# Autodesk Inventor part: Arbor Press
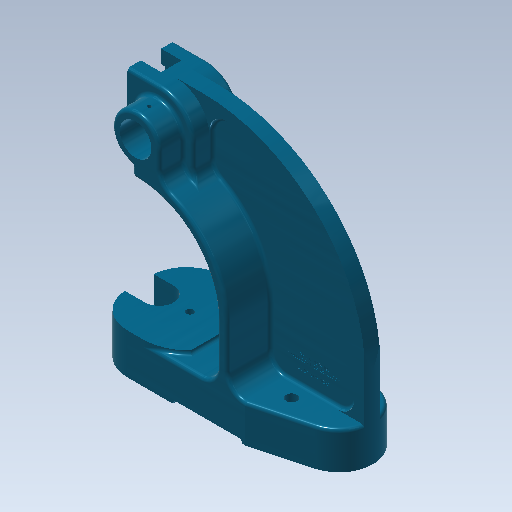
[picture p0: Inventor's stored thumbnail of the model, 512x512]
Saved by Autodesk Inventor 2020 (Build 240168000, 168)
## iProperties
Part Number: Arbor Press
Document SubType Name: Modeling
Created: 2003-11
Designer: Autodesk, Inc.
Manufacturer: Standard
Standards Organization: Custom
Mass: 6013.13 g
Surface Area: 1633.45 cm^2
Volume: 766.003 cm^3
Density: 7.85 g/cm^3
Material: Cast Steel
Appearance: Sky Blue Dark
Control State: 0
Master: False
Checked Out: False
Shininess: 64.0
Length Units: 11272
Angle Units: 11279
Time Units: 11290
Mass Units: 11286
Length Display Precision: 3
Angle Display Precision: 2
Compacted: True
Density: 0.0
Volumn: 0.0
Area: 0.0
PropertySet Name: Model Information
Title: Arbor Press
Author: Autodesk, Inc.
Revision Number: A
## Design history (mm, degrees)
sketch "Sketch7"
  geometry: L1 (0, 0)-(0, 38.1); L2 (0, 38.1)-(79.375, 38.1); L3 (79.375, 38.1)-(79.375, 34.925); L4 (79.375, 34.925)-(117.475, 34.925); L5 (41.275, 165.1)-(11.201, 165.1); L6 (11.201, 165.1)-(11.201, 228.6); L7 (11.201, 228.6)-(66.675, 228.6); L8 (219.075, 76.2)-(219.075, 0); L9 (219.075, 0)-(141.275, 0); L10 (141.275, 0)-(0, 0); L11 (117.475, 34.925)-(117.475, 88.9); A1 r 152.4 centre (66.675, 76.2) between (219.075, 76.2) and (66.675, 228.6); A2 r 76.2 centre (41.275, 88.9) between (117.475, 88.9) and (41.275, 165.1)
  constraints: 22 end point, 8 parallel, 4 point on circle, 4 tangent, 2 centre point, 2 perpendicular, 1 collinear, 1 vertical
  dimensions: "d46" = 79.375 distance of L1.end L2.end; "d47" = 38.1 distance of L1.start L1.end; "d52" = 219.075 distance between parallel lines of L8 L1; "d53" = 228.6 distance between parallel lines of L10 L7; "d54" = 3.175 distance between parallel lines of L4 L2; "d55" = 152.4 radius of A1; "d56" = 76.2 radius of A2; "d57" = 63.5 distance of L5.end L6.end; "d59" = 25.4 horizontal distance of A1.centre A2.centre; "d60" = 30.0736 horizontal distance of A2.centre L5.end
extrude "Extrusion6" new body sketch "Sketch7" distance "d61" = 88.9; taper "d62" = 0 deg
sketch "Sketch8"
  geometry: L1 (207.874, 0)-(55.474, 0) reference; L2 (0, 0)-(55.474, 0) reference; L3 (-11.201, 0)-(68.174, 0) reference; L4 (-11.201, 0)-(-11.201, -88.9) reference; L5 (-11.201, -88.9)-(68.174, -88.9) reference; L6 (207.874, -88.9)-(55.474, -88.9) reference; L7 (207.874, 0)-(207.874, -88.9) reference; L8 (-11.201, -44.45)-(207.874, -44.45); L9 (-11.201, -44.45)-(-11.201, -33.325); L10 (22.123, 0)-(132.907, 0); L11 (132.907, 0)-(184.341, -13.782); L12 (22.123, -88.9)-(132.907, -88.9); L13 (132.907, -88.9)-(184.341, -75.118); L14 (-11.201, -44.45)-(-11.201, -55.575); A1 r 33.325 centre (22.123, -33.325) between (22.123, 0) and (-11.201, -33.325); A2 r 31.75 centre (176.124, -44.45) between (207.874, -44.45) and (184.341, -13.782); A3 r 33.325 centre (22.123, -55.575) between (-11.201, -55.575) and (22.123, -88.9); A4 r 31.75 centre (176.124, -44.45) between (184.341, -75.118) and (207.874, -44.45)
  constraints: 14 end point, 8 point on circle, 5 symmetric about line, 4 centre point, 4 point on line, 4 tangent, 2 midpoint, 1 collinear, 4 other
  dimensions: "d63" = 15 deg angle of L1 L11; "d64" = 33.3248 radius of A1; "d65" = 31.75 radius of A2
extrude "Extrusion7" sketch "Sketch8" extent not by distance; stored distance "d66" = 88.9; taper "d67" = 0 deg
sketch "Sketch9"
  geometry: L1 (141.275, 3.175)-(76.2, 3.175) reference; L2 (144.108, 0)-(195.543, 0) reference; L3 (79.375, 34.925)-(117.475, 34.925) reference; L4 (117.475, 34.925)-(117.475, 88.9) reference; L5 (219.075, 34.925)-(127, 34.925); L6 (219.075, 76.2)-(219.075, 0) reference; L7 (11.201, 228.6)-(11.201, 165.1) reference; L8 (219.075, 34.925)-(219.075, 76.2); L9 (127, 88.9)-(127, 34.925); L10 (73.025, 228.6)-(73.025, 168.529); L11 (33.325, 228.6)-(66.675, 228.6) reference; A1 r 76.2 centre (41.275, 88.9) between (117.475, 88.9) and (41.275, 165.1) reference; A2 r 152.4 centre (66.675, 76.2) between (144.108, 207.463) and (66.675, 228.6) reference; A3 r 152.4 centre (66.675, 76.2) between (195.543, 157.557) and (144.108, 207.463) reference; A4 r 152.401 centre (66.674, 76.2) between (219.075, 76.2) and (195.543, 157.557); A5 r 152.4 centre (66.675, 76.2) between (195.543, 157.557) and (144.108, 207.463); A6 r 85.725 centre (41.275, 88.9) between (127, 88.9) and (73.025, 168.529); A7 r 152.4 centre (66.675, 76.2) between (144.108, 207.463) and (73.025, 228.468)
  constraints: 8 end point, 8 point on circle, 4 centre point, 3 concentric, 2 point on line, 1 collinear
  dimensions: "d86" = 9.525 distance between parallel lines of L9 L4; "d87" = 61.8236 distance between parallel lines of L10 L7; "d88" = 85.725 radius of A6; "d89" = 152.40105 radius of A4
workplane "Work Plane2"
extrude "Extrusion9" cut sketch "Sketch9" distance "d90" = 37.3126; taper "d91" = 0 deg
sketch "Sketch12"
  geometry: L1 (127, 34.925)-(127, 88.9) reference; L2 (144.108, 34.925)-(127, 34.925) reference; L3 (195.543, 34.925)-(144.108, 34.925) reference; L4 (195.543, 34.925)-(218.262, 34.925) reference; L5 (127, 88.9)-(127, 34.925); L6 (218.262, 91.917)-(218.262, 34.925) reference; L7 (208.737, 91.417)-(208.737, 34.925); L8 (66.212, 219.075)-(66.675, 219.075); L9 (208.737, 34.925)-(127, 34.925); L10 (73.025, 168.529)-(73.025, 218.934); L11 (73.025, 228.468)-(73.025, 228.6); A1 r 85.725 centre (41.275, 88.9) between (127, 88.9) and (73.025, 168.529) reference; A2 r 85.725 centre (41.275, 88.9) between (127, 88.9) and (73.025, 168.529); A3 r 152.4 centre (66.675, 76.2) between (195.543, 157.557) and (66.675, 228.6) reference; A4 r 152.401 centre (66.674, 76.2) between (218.262, 91.917) and (195.543, 157.557) reference; A5 r 142.875 centre (66.675, 76.2) between (187.488, 152.472) and (73.025, 218.934); A6 r 142.876 centre (66.674, 76.2) between (208.737, 91.417) and (187.488, 152.472); A7 r 85.725 centre (41.275, 88.9) between (127, 88.9) and (73.025, 168.529) reference; 2 further points; 1 other entity
  constraints: 12 end point, 9 point on circle, 3 centre point, 2 tangent, 1 collinear, 1 concentric, 1 point on line, 1 other
  dimensions: "d93" = 9.525 radial gap between concentric circles of A3 A5; "d94" = 9.525 distance between parallel lines of L6 L7; "d99" = 0 horizontal extent of L10; "d100" = 9.525 radial gap between concentric circles of A4 A6
extrude "Extrusion10" cut sketch "Sketch12" distance "d96" = 3.175; taper "d97" = 0 deg
sketch "Sketch13"
  geometry: L1 (33.325, 165.1)-(11.201, 165.1) reference; L2 (11.201, 228.6)-(11.201, 165.1) reference; L3 (11.201, 228.6)-(33.325, 228.6) reference; L4 (33.325, 228.6)-(66.675, 228.6) reference; L5 (41.275, 165.1)-(33.325, 165.1) reference; L6 (38.1, 165.1)-(38.1, 174.853); L7 (11.201, 196.85)-(77.125, 196.85); L8 (63.5, 196.85)-(63.5, 171.694); L9 (73.025, 168.529)-(73.025, 228.468) reference; L10 (38.1, 165.1)-(11.201, 165.1); L11 (11.201, 165.1)-(11.201, 228.6); L12 (73.025, 228.468)-(73.025, 168.529); L13 (12.066, 228.6)-(66.675, 228.6); A1 r 76.2 centre (41.275, 88.9) between (117.475, 88.9) and (41.275, 165.1) reference; A2 r 152.4 centre (66.675, 76.2) between (73.025, 228.468) and (66.675, 228.6) reference; A3 r 22.225 centre (41.275, 196.85) between (63.5, 196.85) and (38.1, 174.853); A4 r 85.725 centre (41.275, 88.9) between (127, 88.9) and (73.025, 168.529) reference; A5 r 85.725 centre (41.275, 88.9) between (73.025, 168.529) and (63.5, 171.694); A6 r 152.4 centre (66.675, 76.2) between (73.025, 228.468) and (66.675, 228.6)
  constraints: 14 end point, 6 point on circle, 4 perpendicular, 4 point on line, 3 centre point, 3 collinear, 2 concentric, 2 tangent, 1 midpoint
  dimensions: "d101" = 44.45 diameter of A3; "d102" = 30.0736 distance from line of L2 A3.centre; "d103" = 3.175 distance from line of A3.centre L6; "d105" = 9.525 radial gap between concentric circles of A1 A5
extrude "Extrusion11" cut sketch "Sketch13" distance "d106" = 22.225; taper "d107" = 0 deg
mirror "Mirror3"
sketch "Sketch14"
  geometry: L1 (0, 63.5)-(58.272, 63.5) reference; L2 (-8.403, 63.5)-(0, 63.5) reference; L3 (-8.403, 63.5)-(-8.403, 0) reference; L4 (0, 0)-(58.272, 0) reference; L5 (58.272, 0)-(58.272, 63.5) reference; L6 (58.272, 53.975)-(80.497, 53.975) reference; L7 (80.497, 52.504)-(80.497, 10.996) reference; L8 (80.497, 31.75)-(80.497, 53.975) reference; L9 (80.497, 9.753)-(80.497, 0) reference; L10 (80.497, 9.753)-(80.497, 10.996) reference; L11 (80.497, 0)-(58.272, 0) reference; L12 (13.822, 63.5)-(13.822, 9.525); L13 (13.822, 63.5)-(-8.403, 63.5); L14 (-8.403, 63.5)-(-8.403, 9.525); L15 (-8.403, 9.525)-(13.822, 9.525); L16 (0, 0)-(-8.403, 0) reference
  constraints: 8 end point, 3 perpendicular, 1 point on line
  dimensions: "d109" = 44.45 distance between parallel lines of L5 L12; "d111" = 9.525 distance between parallel lines of L4 L15
extrude "Extrusion12" cut sketch "Sketch14" stored distance "d112" = 22.225; taper "d113" = 0 deg
sketch "Sketch16"
  geometry: L1 (-33.325, 174.625)-(-73.025, 174.625) reference; L2 (-33.325, 174.625)-(-33.325, 165.1) reference; L3 (-73.025, 174.625)-(-73.025, 168.529) reference; L4 (-73.025, 168.529)-(-73.025, 174.625); L5 (-73.025, 174.625)-(-41.275, 174.625); A1 r 85.725 centre (-41.275, 88.9) between (-73.025, 168.529) and (-127, 88.9) reference; A2 r 85.725 centre (-41.275, 88.9) between (-41.275, 174.625) and (-73.025, 168.529)
  constraints: 4 end point, 2 collinear, 2 point on circle, 2 tangent, 1 centre point, 1 concentric, 1 point on line
extrude "Extrusion13" cut sketch "Sketch16" distance "d116" = 22.225; taper "d117" = 0 deg
workplane "Work Plane5"
sketch "Sketch17"
  geometry: L1 (11.201, 228.6)-(11.201, 174.625) reference; L2 (66.675, 228.6)-(11.201, 228.6) reference; L3 (73.025, 168.529)-(73.025, 228.468) reference; L4 (11.201, 215.9)-(41.275, 215.9); L5 (41.275, 177.8)-(11.201, 177.8); L6 (33.325, 165.1)-(11.201, 165.1) reference; A1 r 152.4 centre (66.675, 76.2) between (73.025, 228.468) and (66.675, 228.6) reference; A2 r 19.05 centre (41.275, 196.85) between (41.275, 177.8) and (41.275, 215.9)
  constraints: 4 end point, 2 point on circle, 2 point on line, 1 centre point, 1 parallel, 1 tangent
  dimensions: "d120" = 38.1 distance between parallel lines of L5 L4; "d121" = 19.05 radius of A2; "d122" = 12.7 distance of L1.start L4.start; "d123" = 12.7 distance of L6.end L5.end; "d124" = 30.0736 distance from line of L1 A2.centre
extrude "Extrusion14" cut sketch "Sketch17" stored distance "d125" = 25.4; taper "d126" = 0 deg
sketch "Sketch18"
  geometry: C1 r 14.879 at (41.275, 196.85); A1 r 22.225 centre (41.275, 196.85) between (63.5, 196.85) and (33.325, 217.604) reference
  constraints: 1 centre point, 1 coincident
  dimensions: "d127" = 29.758 diameter of C1
extrude "Extrusion15" cut sketch "Sketch18" distance "d128" = 38.1; taper "d129" = 0 deg
sketch "Sketch19"
  geometry: C1 r 9.538 at (41.275, 196.85); A1 r 22.225 centre (41.275, 196.85) between (63.5, 196.85) and (33.325, 217.604) reference; 2 further points
  constraints: 1 centre point, 1 coincident
  dimensions: "d130" = 19.0754 diameter of C1
extrude "Extrusion16" cut sketch "Sketch19" distance "d131" = 25.4; taper "d132" = 0 deg
fillet "Fillet2" dims "d134" = 15.875
fillet "Fillet3" dims "d135" = 15.875
sketch "Sketch20"
  geometry: L1 (11.201, 228.6)-(66.675, 228.6) reference; L2 (73.025, 228.468)-(73.025, 178.646) reference; L3 (41.275, 228.6)-(66.675, 228.6); L4 (73.025, 228.468)-(73.025, 196.85); C1 r 9.538 at (41.275, 196.85) reference; A1 r 31.75 centre (41.275, 196.85) between (73.025, 196.85) and (41.275, 228.6); A2 r 152.4 centre (66.675, 76.2) between (73.025, 228.468) and (66.675, 228.6) reference; A3 r 152.4 centre (66.675, 76.2) between (73.025, 228.468) and (66.675, 228.6)
  constraints: 4 end point, 4 point on circle, 2 centre point, 2 point on line, 2 tangent, 1 coincident, 1 collinear, 1 concentric
extrude "Extrusion17" cut sketch "Sketch20" distance "d136" = 15.0876; taper "d137" = 0 deg
mirror "Mirror4"
fillet "Fillet4" dims "d138" = 15.875
fillet "Fillet5" dims "d139" = 3.175
fillet "Fillet6" dims "d140" = 3.175
fillet "Fillet7" dims "d141" = 15.875
sketch "Sketch22"
  geometry: L1 (-79.375, 55.575)-(-79.375, 33.325) reference; L2 (-46.05, 0)-(0, 0) reference; L3 (-46.05, 88.9)-(0, 88.9) reference; L4 (-79.375, 44.45)-(-18.816, 44.45); L5 (-60.325, 57.944)-(-79.375, 57.944); L6 (-79.375, 30.956)-(-60.325, 30.956); L7 (-79.375, 57.944)-(-79.375, 30.956); A1 r 33.325 centre (-46.05, 55.575) between (-46.05, 88.9) and (-79.375, 55.575) reference; A2 r 33.325 centre (-46.05, 33.325) between (-79.375, 33.325) and (-46.05, 0) reference; A3 r 13.494 centre (-60.325, 44.45) between (-60.325, 30.956) and (-60.325, 57.944)
  constraints: 8 end point, 3 perpendicular, 3 point on line, 2 point on circle, 2 tangent, 1 centre point, 1 midpoint, 1 parallel
  dimensions: "d147" = 26.9875 diameter of A3; "d148" = 19.05 distance of L4.start A3.centre
extrude "Extrusion19" cut sketch "Sketch22" stored distance "d149" = 3.175; taper "d150" = 0 deg
sketch "Sketch23"
  geometry: L1 (0, 88.9)-(0, 0) reference; L2 (-46.05, 0)-(0, 0) reference; L3 (-60.325, 44.45)-(-10.181, 44.45); L4 (0, 13.341)-(0, 0); L5 (0, 0)-(-31.75, 0); A1 r 44.45 centre (-31.75, 44.45) between (-31.75, 0) and (0, 13.341); A2 r 13.494 centre (-60.325, 44.45) between (-60.325, 30.956) and (-60.325, 57.944) reference
  constraints: 6 end point, 3 point on line, 2 point on circle, 1 centre point, 1 parallel, 1 perpendicular
  dimensions: "d151" = 88.9 diameter of A1; "d153" = 28.575 distance of A1.centre L3.start
extrude "Extrusion20" cut sketch "Sketch23" distance "d154" = 3.175; taper "d155" = 0 deg
mirror "Mirror5"
fillet "Fillet10" dims "d157" = 15.875
fillet "Fillet11" dims "d158" = 15.875
fillet "Fillet12" dims "d159" = 15.875
fillet "Fillet15" dims "d162" = 15.875
sketch "Sketch24"
  geometry: L1 (-33.241, 57.944)-(-14.275, 57.944) reference; L2 (-14.275, 30.956)-(-33.241, 30.956) reference; L3 (110.783, 0)-(0, 0) reference; L4 (162.218, 13.782)-(110.783, 0) reference; L5 (110.783, 88.9)-(162.218, 75.118) reference; L6 (110.783, 88.9)-(0, 88.9) reference; L7 (0, 80.975)-(109.74, 80.975); L8 (109.74, 80.975)-(160.167, 67.463); L9 (160.167, 21.437)-(109.74, 7.925); L10 (109.74, 7.925)-(0, 7.925); L11 (-23.221, 23.031)-(-14.275, 23.031); L12 (-14.275, 65.869)-(-23.221, 65.869); A1 r 13.494 centre (-14.275, 44.45) between (-14.275, 30.956) and (-14.275, 57.944) reference; A2 r 33.325 centre (0, 33.325) between (-33.241, 30.956) and (0, 0) reference; A3 r 31.75 centre (154, 44.45) between (162.218, 13.782) and (162.218, 75.118) reference; A4 r 33.325 centre (0, 55.575) between (0, 88.9) and (-33.241, 57.944) reference; A5 r 23.825 centre (154, 44.45) between (160.167, 21.437) and (160.167, 67.463); A6 r 25.4 centre (0, 33.325) between (-23.221, 23.031) and (0, 7.925); A7 r 21.419 centre (-14.275, 44.45) between (-14.275, 23.031) and (-14.275, 65.869); A8 r 25.4 centre (0, 55.575) between (0, 80.975) and (-23.221, 65.869)
  constraints: 12 end point, 8 point on circle, 4 centre point, 9 other
  dimensions: "d163" = 7.9248 distance between parallel lines of L7 L6
extrude "Extrusion21" cut sketch "Sketch24" distance "d164" = 26.9875; taper "d165" = 0 deg
sketch "Sketch25"
  geometry: L1 (144.108, 0)-(33.325, 0) reference; L2 (33.325, 0)-(0.084, 0) reference; L3 (0.084, 38.1)-(0.084, 0) reference; L4 (76.284, 0)-(76.284, 3.175); L5 (76.284, 3.175)-(141.359, 3.175); L6 (141.359, 3.175)-(141.359, 0)
  constraints: 6 end point, 2 parallel, 2 point on line, 1 perpendicular
  dimensions: "d166" = 76.2 distance between parallel lines of L3 L4; "d167" = 65.0748 distance of L4.end L5.end; "d168" = 3.175 distance between parallel lines of L1 L5
extrude "Extrusion22" cut sketch "Sketch25" extent not by distance; stored distance "d169" = 26.9875; taper "d170" = 0 deg
sketch "Sketch27"
  geometry: L1 (-23.221, 65.869)-(-14.275, 65.869) reference; L2 (-14.275, 23.031)-(-23.221, 23.031) reference; L3 (0, 7.925)-(109.74, 7.925) reference; L4 (109.74, 7.925)-(160.167, 21.437) reference; L5 (160.167, 67.463)-(109.74, 80.975) reference; L6 (109.74, 80.975)-(0, 80.975) reference; L7 (27, 80.975)-(27, 7.925); L8 (103.226, 80.975)-(103.226, 7.925); L9 (27, 80.975)-(103.226, 80.975); L10 (27, 7.925)-(103.226, 7.925); A1 r 25.4 centre (0, 55.575) between (0, 80.975) and (-23.221, 65.869) reference; A2 r 21.419 centre (-14.275, 44.45) between (-14.275, 23.031) and (-14.275, 65.869) reference; A3 r 25.4 centre (0, 33.325) between (-23.221, 23.031) and (0, 7.925) reference; A4 r 23.825 centre (154, 44.45) between (160.167, 21.437) and (160.167, 67.463) reference; A5 r 31.75 centre (154, 44.45) between (162.218, 13.782) and (162.218, 75.118) reference; 1 further point
  constraints: 8 end point, 4 point on line, 2 collinear, 2 perpendicular
  dimensions: "d176" = 60.325 distance from line of L7 point (-33.325, 0); "d178" = 50.7746 distance from line of A4.centre L8
extrude "Extrusion23" join sketch "Sketch27" distance "d179" = 12.6873; taper "d180" = 0 deg
workplane "Work Plane7"
sketch "Sketch28"
  geometry: L1 (-136.55, 14.3)-(-136.55, 26.988) reference; L2 (-60.325, 14.3)-(-136.55, 14.3) reference; L3 (-136.55, 26.988)-(-114.575, 14.3); L4 (-114.575, 14.3)-(-136.55, 14.3); L5 (-136.55, 14.3)-(-136.55, 26.988)
  constraints: 6 end point, 1 collinear, 1 perpendicular, 1 point on line
  dimensions: "d182" = 30 deg angle of L2 L3
extrude "Extrusion24" cut sketch "Sketch28" stored distance "d183" = 73.0504; taper "d184" = 0 deg
fillet "Fillet17" dims "d185" = 3.175
sketch "Sketch29"
  geometry: L1 (-58.272, 0)-(0, 0) reference; L2 (0, 0)-(0, 63.5) reference; L3 (-44.45, 63.5)-(0, 63.5) reference; L4 (-44.45, 63.5)-(-44.45, 9.525) reference; L5 (-58.272, 0)-(-58.272, 9.525) reference; L6 (-9.525, 50.8)-(-9.525, 12.7) reference; L7 (-9.525, 12.7)-(-34.925, 12.7) reference; L8 (-34.925, 12.7)-(-34.925, 50.8) reference; L9 (-34.925, 50.8)-(-9.525, 50.8) reference; L10 (-22.225, 63.5)-(-22.225, 0); L11 (-6.35, 57.15)-(-61.925, 57.15); L12 (-34.925, 31.75)-(-9.525, 31.75); L13 (-44.45, 9.525)-(-58.272, 9.525) reference; 3 further points
  constraints: 6 end point, 3 midpoint, 2 perpendicular, 2 point on line, 2 symmetric about line
  dimensions: "d186" = 31.75 distance of L11.start point (-38.1, 57.15); "d187" = 15.875 distance from line of L11.start L10; "d188" = 6.35 distance from line of L3 L11.start
hole "Hole1" sketch "Sketch29" at (-38.1, 57.15), (-6.35, 57.15), (-38.1, 6.35), (-6.35, 6.35) diameter "d189" = 4.9784; stored, may be unused: countersink angle "d193" = 82 deg, drill point angle "d195" = 118 deg; dims "d190" = 12.7, "d191" = 9.525, "d192" = 6.35, "d194" = 19.1008
sketch "Sketch30"
  geometry: L1 (-31.75, -49.954)-(-31.75, -31.75) reference; L2 (30.074, -53.975)-(0, -53.975) reference; L3 (30.074, 0)-(30.074, -53.975) reference; L4 (0, 0)-(30.074, 0) reference; L5 (20.549, -19.05)-(20.549, -44.45); L6 (30.074, -63.5)-(7.95, -63.5) reference; C1 r 9.538 at (0, -31.75) reference; A1 r 31.75 centre (0, -31.75) between (0, 0) and (-31.75, -31.75) reference; A2 r 15.875 centre (-47.625, -49.954) between (-40.184, -63.976) and (-31.75, -49.954) reference; A3 r 85.725 centre (0, -139.7) between (0, -53.975) and (-40.184, -63.976) reference; 1 further point
  constraints: 2 end point
  dimensions: "d196" = 25.4 distance of L5.start L5.end; "d197" = 9.525 distance from line of L3 L5.start; "d255" = 6.35 vertical distance of point (30.074, -50.8) L5.end; "d256" = 20.5486 horizontal distance of A1.centre L5.end
hole "Hole2" sketch "Sketch30" at (20.549, -19.05), (20.549, -44.45) diameter "d199" = 3.9624; stored, may be unused: countersink angle "d203" = 82 deg, drill point angle "d205" = 118 deg; dims "d200" = 12.7, "d201" = 9.525, "d202" = 6.35, "d204" = 19.05
sketch "Sketch31"
  geometry: C1 r 9.538 at (0, -31.75) reference; C2 r 17.45 at (0, -31.75)
  constraints: 1 centre point, 1 coincident
  dimensions: "d206" = 17.4498 radius of C2
extrude "Extrusion25" join sketch "Sketch31" distance "d207" = 9.525; taper "d208" = 0 deg
fillet "Fillet19" dims "d210" = 3.175
sketch "Sketch32"
  geometry: L1 (-42.85, 29.362)-(-42.85, 38.887) reference; L2 (-25.4, 38.887)-(-25.4, 5.475); L3 (-42.85, 38.887)-(-7.95, 38.887) reference; 1 further point
  constraints: 2 end point, 1 parallel, 1 point on line
  dimensions: "d290" = 4.7625 distance from line of L3 point (-25.4, 34.125)
hole "Hole3" sketch "Sketch32" at (-25.4, 34.125) diameter "d212" = 3.175; stored, may be unused: countersink angle "d216" = 82 deg, drill point angle "d218" = 118 deg; dims "d213" = 12.7, "d214" = 9.525, "d215" = 6.35, "d217" = 25.4
sketch "Sketch34"
  geometry: A1 r 13.494 centre (-173.812, 7.137) between (-173.812, -6.356) and (-173.812, 20.631) reference; 1 further point
  dimensions: "d228" = 142.875 horizontal distance of point (-30.937, -11.913) A1.centre; "d229" = 19.05 vertical distance of point (-30.937, -11.913) A1.centre
hole "Hole5" sketch "Sketch34" at (-30.937, -11.913) diameter "d230" = 10.3124; stored, may be unused: countersink angle "d234" = 82 deg, drill point angle "d236" = 118 deg; dims "d231" = 12.7, "d232" = 9.525, "d233" = 6.35, "d235" = 12.7
mirror "Mirror6"
sketch "Sketch35"
  geometry: A1 r 13.494 centre (18.966, -13.494) between (18.966, -26.988) and (18.966, 0) reference; 1 further point
  dimensions: "d237" = 28.575 distance of point (47.541, -13.494) A1.centre; "d238" = 0 vertical distance of A1.centre point (47.541, -13.494)
hole "Hole6" sketch "Sketch35" at (47.541, -13.494) diameter "d239" = 6.731; stored, may be unused: countersink angle "d243" = 82 deg, drill point angle "d245" = 118 deg; dims "d240" = 12.7, "d241" = 9.525, "d242" = 6.35, "d244" = 12.7
sketch "Sketch36"
  geometry: L1 (-58.272, 0)-(0, 0) reference; L2 (0, 0)-(0, 63.5) reference; L3 (-44.45, 63.5)-(0, 63.5) reference; L4 (-44.45, 63.5)-(-44.45, 9.525) reference; L5 (-58.272, 0)-(-58.272, 9.525) reference; L6 (-9.525, 50.8)-(-9.525, 12.7) reference; L7 (-9.525, 12.7)-(-34.925, 12.7) reference; L8 (-34.925, 12.7)-(-34.925, 50.8) reference; L9 (-34.925, 50.8)-(-9.525, 50.8) reference; L10 (-31.75, 63.5)-(-31.75, 50.8); L11 (-12.725, 63.5)-(-12.725, 50.8); L12 (-34.925, 31.75)-(-9.525, 31.75); L13 (-22.225, 50.8)-(-22.225, 31.75); L14 (-31.75, 63.5)-(-12.725, 63.5); L15 (-31.75, 50.8)-(-12.725, 50.8); L16 (-44.45, 9.525)-(-58.272, 9.525) reference; C1 r 2.489 at (-38.1, 6.35) reference; C2 r 2.489 at (-38.1, 57.15) reference; C3 r 2.489 at (-6.35, 57.15) reference; C4 r 2.489 at (-6.35, 6.35) reference
  constraints: 12 end point, 4 midpoint, 4 point on line, 3 perpendicular, 1 parallel
  dimensions: "d246" = 19.0246 distance between parallel lines of L11 L10; "d247" = 9.4996 distance between parallel lines of L11 L13
extrude "Extrusion26" cut sketch "Sketch36" distance "d248" = 19.1008; taper "d249" = 0 deg
workplane "Work Plane8"
mirror "Mirror7"
sketch "Sketch37"
  geometry: L1 (-11.201, 174.625)-(-41.275, 174.625) reference; L2 (-30.302, 165.1)-(-11.201, 165.1) reference; L3 (-11.201, 165.1)-(-11.201, 177.8) reference; L4 (-11.201, 174.625)-(-11.201, 165.1); L5 (-41.275, 174.625)-(-11.201, 174.625); L6 (-41.275, 174.625)-(-41.275, 165.1); L7 (-11.201, 165.1)-(-41.275, 165.1)
  constraints: 8 end point, 2 collinear, 2 perpendicular
extrude "Extrusion27" join sketch "Sketch37" distance "d251" = 12.7; taper "d252" = 0 deg
delete_face "Delete Face1"
sketch "Sketch39"
  geometry: L1 (180.803, 172.743)-(244.935, 172.743); L2 (244.935, 172.743)-(244.935, 72.014); L3 (244.935, 72.014)-(180.803, 72.014); L4 (180.803, 72.014)-(180.803, 172.743)
  constraints: 8 end point, 2 parallel, 1 horizontal, 1 perpendicular
extrude "Extrusion28" cut sketch "Sketch39" distance "d264" = 25.4; taper "d265" = 0 deg
mirror "Mirror8"
fillet "Fillet21" dims "d266" = 3.175
fillet "Fillet22" dims "d267" = 3.175
fillet "Fillet23" dims "d268" = 3.175
sketch "Sketch40"
  geometry: L1 (-3.175, -34.138)-(-30.956, -34.138) reference; L2 (-3.175, -34.138)-(-3.175, -18.263) reference; L3 (-30.956, -18.263)-(-3.175, -18.263) reference; L4 (-30.956, -34.138)-(-30.956, -18.263) reference; L5 (-47.625, -18.263)-(-47.625, -34.138) reference; L6 (-23.812, 34.125)-(-23.812, -34.138); L7 (-6.35, -37.313)-(-44.45, -37.313) reference; C1 r 1.587 at (-23.812, -26.213); 2 further points
  constraints: 2 end point, 2 point on line, 1 centre point, 1 perpendicular
  dimensions: "d272" = 3.175 diameter of C1; "d275" = 11.0998 distance from line of L7 C1.centre
extrude "Extrusion29" cut sketch "Sketch40" distance "d276" = 25.4; taper "d277" = 0 deg
sketch "Sketch41"
  geometry: L1 (22.225, 60.325)-(22.225, 9.525) reference; L2 (22.225, 9.525)-(0, 9.525) reference; L3 (0, 0)-(0, 9.525) reference; L4 (0, 0)-(34.925, 0) reference; L5 (34.925, 0)-(34.925, 12.7) reference; L6 (31.75, 12.7)-(31.75, 50.8) reference; L7 (34.925, 50.8)-(34.925, 63.5) reference; L8 (25.4, 63.5)-(34.925, 63.5) reference; L9 (22.225, 9.525)-(22.225, 0); L10 (22.225, 0)-(0, 0); L11 (0, 0)-(0, 9.525); L12 (0, 9.525)-(22.225, 9.525); L13 (34.925, 12.7)-(31.75, 12.7) reference; L14 (31.75, 50.8)-(34.925, 50.8) reference; C1 r 2.489 at (28.575, 57.15) reference; C2 r 2.489 at (28.575, 6.35) reference; A1 r 3.175 centre (25.4, 60.325) between (25.4, 63.5) and (22.225, 60.325) reference
  constraints: 8 end point, 2 collinear, 2 perpendicular, 1 point on line
extrude "Extrusion30" cut sketch "Sketch41" distance "d278" = 26.8986; taper "d279" = 0 deg
fillet "Fillet27" dims "d280" = 3.175
fillet "Fillet28" dims "d281" = 3.175
fillet "Fillet30" dims "d283" = 3.175
sketch "Sketch42"
  geometry: L1 (3.175, -31.75)-(3.175, -22.225) reference; L2 (-102.833, -196.85)-(-102.833, -165.1) reference; L3 (-102.833, -196.85)-(-100.084, -196.85) reference; L4 (-100.084, -193.675)-(-35.009, -193.675) reference; L5 (7.95, -158.75)-(7.95, -196.85) reference; L6 (7.95, -158.75)-(-6.35, -158.75) reference; L7 (3.175, -22.225)-(3.175, -17.159); L8 (-17.45, 0)-(-17.45, -24.02); L9 (0, -22.225)-(3.175, -22.225); L10 (-102.833, -165.1)-(-101.6, -165.1) reference; L11 (-82.55, -146.05)-(-82.55, -107.95) reference; L12 (-60.325, -165.1)-(-6.35, -165.1) reference; L13 (-79.375, -107.95)-(-79.375, -146.05) reference; L14 (3.175, -28.575)-(0, -28.575) reference; L15 (3.175, -28.575)-(3.175, -25.4) reference; L16 (0, -25.4)-(3.175, -25.4) reference; L17 (-100.084, -196.85)-(-100.084, -193.675) reference; L18 (-35.009, -193.675)-(-35.009, -196.85) reference; L19 (-35.009, -196.85)-(7.95, -196.85) reference; L20 (-6.35, -158.75)-(-6.35, -165.1) reference; A1 r 17.45 centre (0, 0) between (3.175, -17.159) and (-17.45, 0) reference; A2 r 17.45 centre (0, 0) between (-17.45, 0) and (3.175, -17.159); A3 r 85.725 centre (0, -107.95) between (0, -22.225) and (-17.45, -24.02); A4 r 82.55 centre (0, -107.95) between (0, -25.4) and (-82.55, -107.95) reference; A5 r 19.05 centre (-101.6, -146.05) between (-101.6, -165.1) and (-82.55, -146.05) reference; A6 r 19.05 centre (-60.325, -146.05) between (-79.375, -146.05) and (-60.325, -165.1) reference; A7 r 79.375 centre (0, -107.95) between (0, -28.575) and (-79.375, -107.95) reference
  constraints: 6 end point, 6 point on circle, 3 tangent, 2 centre point, 1 concentric, 1 parallel, 1 perpendicular
extrude "Extrusion31" join sketch "Sketch42" distance "d284" = 9.525; taper "d285" = 0 deg
fillet "Fillet31" dims "d286" = 3.175
fillet "Fillet32" dims "d287" = 3.175
fillet "Fillet33" dims "d288" = 3.175
fillet "Fillet34" dims "d289" = 3.175
sketch "Sketch43"
  geometry: L1 (123.521, 60.955)-(212.511, 60.955); L2 (212.511, 60.955)-(212.511, 48.209); L3 (212.511, 48.209)-(123.521, 48.209); L4 (123.521, 48.209)-(123.521, 60.955)
  constraints: 2 other
emboss "Emboss1" sketch "Sketch43" dims "d293" = 2.54, "d294" = 0
fillet "Fillet35" dims "d295" = 3.175
fillet "Fillet36" dims "d296" = 3.175
fillet "Fillet37" dims "d297" = 3.175
fillet "Fillet38" dims "d298" = 3.175
fillet "Fillet39" dims "d299" = 3.175
body "Solid1"
node "Projected Loop4"
node "Projected Loop5"
node "Projected Loop6"
node "Projected Loop7"
node "Projected Loop8"
node "Projected Loop9"
node "Projected Loop10"
node "Projected Loop11"
other parameters: "d32" = 47.625, "d33" = 47.625, "d39" = 47.625, "d76" = 61.8236, "d80" = -44.45, "d98" = 31.75, "d118" = -22.225, "d181" = -44.45, "d250" = -31.75
